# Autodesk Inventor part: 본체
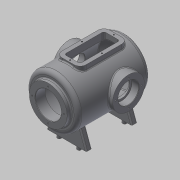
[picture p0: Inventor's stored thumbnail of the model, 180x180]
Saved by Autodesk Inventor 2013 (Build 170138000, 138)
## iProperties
Created: 2016-02
Part Number: 본체
Material: 알루미늄 6061
Document SubType Name: Modeling
Designer: mduedu
Density: 1 g/cm^3
Author: mduedu
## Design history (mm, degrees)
sketch "스케치2"
  geometry: L1 (0, 100)-(0, -100); L2 (65, -75.993)-(65, 100); L3 (65, 100)-(0, 100); A1 r 100 centre (0, 0) between (0, -100) and (65, -75.993); 2 further points
  constraints: 6 end point, 2 midpoint, 2 point on circle, 1 centre point, 1 coincident, 1 horizontal, 1 parallel, 1 vertical
  dimensions: "d3" = 200 distance of L1.start L1.end; "d5" = 130 diameter of L2 L1; "d6" = 100 radius of A1
revolve "회전1" sketch "스케치2" stored, may be unused: angle "d7" = 90 deg
sketch "스케치3"
  geometry: C1 r 47.5 at (0, 0); 1 further point
  constraints: 1 centre point, 1 coincident
  dimensions: "d8" = 95 diameter of C1
extrude "돌출2" join sketch "스케치3" distance "d10" = 10; taper "d11" = 0 deg
sketch "스케치5"
  geometry: L1 (47.5, 110)-(47.5, 100) reference; L2 (47.5, 100)-(65, 100) reference; L3 (65, 100)-(65, -75.993) reference; L4 (-65, -75.993)-(-65, 100) reference; L5 (-65, 100)-(-47.5, 100) reference; L6 (-47.5, 100)-(-47.5, 110) reference; L7 (-47.5, 110)-(47.5, 110) reference; L8 (55, 85)-(55, -71.239); L9 (0, 85)-(55, 85); L10 (0, 85)-(0, -90); A1 r 100 centre (0, 0) between (0, -100) and (65, -75.993) reference; A2 r 100 centre (0, 0) between (-65, -75.993) and (0, -100) reference; A3 r 90 centre (0, 0) between (0, -90) and (55, -71.239); 1 further point
  constraints: 6 end point, 2 point on circle, 1 centre point, 1 parallel, 1 perpendicular, 1 point on line, 1 vertical
  dimensions: "d13" = 10 distance between parallel lines of L3 L8; "d14" = 10 radial gap between concentric circles of A3 A1; "d15" = 15 distance between parallel lines of L9 L2
revolve "회전2" sketch "스케치5" stored, may be unused: angle "d16" = 90 deg
hole "구멍1" diameter "d19" = 65; stored, may be unused: countersink angle "d23" = 90 deg, drill point angle "d25" = 118 deg; dims "d17" = 10, "d18" = 10, "d20" = 6, "d21" = 4, "d22" = 2, "d24" = 8
node "작업 평면1"
sketch "스케치6"
  geometry: L1 (47.5, 110)-(-47.5, 110) reference; C1 r 40 at (0, -17); 1 further point
  constraints: 1 centre point, 1 vertical alignment
  dimensions: "d27" = 80 diameter of C1; "d29" = 127 distance from line of C1.centre L1
extrude "돌출3" join sketch "스케치6" stored distance "d30" = 10; taper "d31" = 0 deg
hole "구멍2" diameter "d34" = 42; stored, may be unused: countersink angle "d38" = 90 deg, drill point angle "d40" = 118 deg; dims "d32" = 10, "d33" = 10, "d35" = 6, "d36" = 52, "d37" = 18, "d39" = 8
sketch "스케치7" dims "d41" = 65
  geometry: C1 r 40 at (0, 0) reference; 3 further points
  constraints: 2 vertical alignment, 1 coincident, 2 other
hole "구멍3" sketch "스케치7" at (0, 32.5) diameter "d43" = 3.242; stored, may be unused: countersink angle "d47" = 90 deg, drill point angle "d49" = 118 deg; dims "d44" = 11, "d45" = 13, "d46" = 18, "d48" = 13
sketch "스케치8" dims "d53" = 80
  geometry: 3 further points
  constraints: 2 vertical alignment, 1 coincident, 2 other
hole "구멍4" sketch "스케치8" at (0, 40) diameter "d56" = 3.242; stored, may be unused: countersink angle "d60" = 90 deg, drill point angle "d62" = 118 deg; dims "d57" = 11, "d58" = 13, "d59" = 18, "d61" = 13
fillet "모깎기1" dims "d66" = 10
fillet "모깎기2" dims "d67" = 3
fillet "모깎기3" dims "d68" = 0.3
chamfer "모따기1" distance "d69" = 1; stored, may be unused: second distance "d70" = 2, angle "d71" = 45 deg
node "작업 평면5"
sketch "스케치10"
  geometry: L1 (-50, -64)-(50, -64); L2 (50, -64)-(50, -50); L3 (50, -50)-(-50, -50); L4 (-50, -50)-(-50, -64); L5 (-50, 0)-(50, 0); L6 (-50, 64)-(50, 64); L7 (50, 64)-(50, 50); L8 (50, 50)-(-50, 50); L9 (-50, 50)-(-50, 64); 2 further points
  constraints: 18 end point, 4 symmetric about line, 2 parallel, 2 perpendicular, 1 coincident, 1 horizontal, 1 midpoint
  dimensions: "d80" = 14 distance of L3.end L1.start; "d82" = 100 distance of L1.start L1.end; "d130" = 50 horizontal distance of L3.end point (0, 0); "d131" = 50 horizontal distance of L3.end point (0, 0); "d132" = 100 distance of L5.start L5.end
extrude "돌출5" join sketch "스케치10" stored distance "d84" = 10; taper "d85" = 0 deg
feature "면 기울기3" dims angle "d135" = 20 deg
sketch "스케치11"
  geometry: L1 (-85, -50)-(-85, 50); L2 (-65, 90)-(-65, -71.239) reference; L3 (-100, -50)-(-41.533, -50) reference; L4 (-100, 50)-(-41.533, 50) reference; 1 further point
  constraints: 2 end point, 2 point on line
  dimensions: "d87" = 20 distance between parallel lines of L1 L2
feature "리브1" sketch "스케치11" dims "d88" = 1, "d89" = 8, "d90" = 0, "d91" = 0, "d92" = 1, "d93" = 1
fillet "모깎기5" dims "d103" = 3
fillet "모깎기6" dims "d105" = 3
node "작업 평면6"
sketch "스케치15"
  geometry: L1 (-30, 60)-(30, 60); L2 (30, 60)-(30, -60); L3 (30, -60)-(-30, -60); L4 (-30, -60)-(-30, 60); 2 further points
  constraints: 8 end point, 2 parallel, 1 horizontal, 1 midpoint, 1 perpendicular, 1 vertical alignment
  dimensions: "d110" = 60 distance of L2.end L3.end; "d112" = 60 distance from line of L3 point (0, 0); "d113" = 120 distance of L1.end L2.end
extrude "돌출8" join sketch "스케치15" stored distance "d114" = 10; taper "d115" = 0 deg
fillet "모깎기7" dims "d116" = 15
sketch "스케치16"
  geometry: L1 (-30, -45)-(-30, 45) reference; L2 (30, 45)-(30, -45) reference; L3 (-15, 60)-(15, 60) reference; L4 (15, -60)-(-15, -60) reference; L5 (-20, -45)-(-20, 45); L6 (-15, 50)-(15, 50); L7 (20, 45)-(20, -45); L8 (15, -50)-(-15, -50); A1 r 15 centre (-15, -45) between (-30, -45) and (-15, -60) reference; A2 r 15 centre (-15, 45) between (-15, 60) and (-30, 45) reference; A3 r 15 centre (15, 45) between (30, 45) and (15, 60) reference; A4 r 15 centre (15, -45) between (15, -60) and (30, -45) reference; A5 r 5 centre (-15, -45) between (-20, -45) and (-15, -50); A6 r 5 centre (-15, 45) between (-15, 50) and (-20, 45); A7 r 5 centre (15, 45) between (20, 45) and (15, 50); A8 r 5 centre (15, -45) between (15, -50) and (20, -45)
  constraints: 8 end point, 8 point on circle, 4 centre point, 7 other
  dimensions: "d137" = 10 distance between parallel lines of L5 L1
extrude "돌출9" cut sketch "스케치16" stored distance "d118" = 10; taper "d119" = 0 deg
fillet "모깎기8" dims "d120" = 3
sketch "스케치17"
  geometry: L1 (-30, -45)-(-30, 45) reference; L2 (30, 45)-(30, -45) reference; L3 (-20, 45)-(-20, -45) reference; L4 (-15, -50)-(15, -50) reference; L5 (20, -45)-(20, 45) reference; L6 (15, 50)-(-15, 50) reference; L7 (-15, 60)-(15, 60) reference; L8 (15, -60)-(-15, -60) reference; L9 (15, 55)-(-15, 55); L10 (-25, 45)-(-25, -45); L11 (-15, -55)-(15, -55); L12 (25, -45)-(25, 45); A1 r 5 centre (-15, 45) between (-15, 50) and (-20, 45) reference; A2 r 5 centre (-15, -45) between (-20, -45) and (-15, -50) reference; A3 r 5 centre (15, -45) between (15, -50) and (20, -45) reference; A4 r 5 centre (15, 45) between (20, 45) and (15, 50) reference; A5 r 15 centre (-15, 45) between (-15, 60) and (-30, 45) reference; A6 r 15 centre (15, 45) between (30, 45) and (15, 60) reference; A7 r 15 centre (15, -45) between (15, -60) and (30, -45) reference; A8 r 15 centre (-15, -45) between (-30, -45) and (-15, -60) reference; A9 r 10 centre (-15, 45) between (-15, 55) and (-25, 45); A10 r 10 centre (-15, -45) between (-25, -45) and (-15, -55); A11 r 10 centre (15, -45) between (15, -55) and (25, -45); A12 r 10 centre (15, 45) between (25, 45) and (15, 55); 4 further points
  constraints: 8 end point, 8 point on circle, 4 centre point, 4 midpoint, 7 other
  dimensions: "d138" = 5 distance between parallel lines of L9 L7
hole "구멍5" sketch "스케치17" at (0, 55), (25, 0), (0, -55), (-25, 0) diameter "d122" = 3.242; stored, may be unused: countersink angle "d126" = 90 deg, drill point angle "d128" = 118 deg; dims "d123" = 9, "d124" = 13, "d125" = 18, "d127" = 11
fillet "모깎기9" dims "d129" = 3
sketch "스케치18"
  geometry: L1 (-46.807, 50)-(46.807, 50) reference; L2 (50, 53)-(50, 61) reference; L3 (46.807, 64)-(-46.807, 64) reference; L4 (-50, 61)-(-50, 53) reference; L5 (-50, 57)-(50, 57); L6 (0, 64)-(0, 50); C1 r 5 at (-25, 57); C2 r 5 at (25, 57); 5 further points; 4 other entities
  constraints: 4 end point, 4 midpoint, 2 centre point, 1 point on line, 1 symmetric about line, 5 other
  dimensions: "d139" = 10 diameter of C1; "d141" = 25 distance from line of L6 C1.centre; "d147" = 57 vertical distance of C2.centre point (0, 0) (derived)
extrude "돌출10" join sketch "스케치18" distance "d142" = 10; taper "d143" = 0 deg
chamfer "모따기2" distance "d144" = 1; stored, may be unused: second distance "d145" = 2, angle "d146" = 45 deg
node "작업 평면7"
fillet "모깎기10" dims "d148" = 0.5
node "솔리드2"
pattern_circular "원형 패턴1" dims angle "d51" = 360 deg
mirror "대칭1"
pattern_circular "원형 패턴2" dims angle "d64" = 360 deg
mirror "대칭2"
node "투영된 루프1"
node "절단 모서리 투영1"
node "절단 모서리 투영2"
node "절단 모서리 투영3"
other parameters: "d26" = 75
